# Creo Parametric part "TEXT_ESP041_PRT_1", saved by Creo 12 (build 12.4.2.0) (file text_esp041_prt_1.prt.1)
Units: Custom; MM, KILOGRAM, SECS

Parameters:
  PTC_WM_ITERATION = "0"
  PTC_WM_VERSION = "-.0"
  PTC_WM_LIFECYCLE_STATE = "In Work"
  PTC_WM_LIFECYCLE = "MO_CADDocument"
  PTC_WM_CREATED_BY = "Maximilian Roepper (Z0017RMS: MO)"
  PTC_WM_CREATED_ON = "18-Sep-26 11:36:42 AM"
  PTC_WM_MODIFIED_BY = "Maximilian Roepper (Z0017RMS: MO)"
  PTC_WM_MODIFIED_ON = "18-Sep-26 11:36:46 AM"
  PDMLINKNUMBER = "PDM000071454912"
  PTC_WM_NAME = "text_esp041_prt_1.prt"
  PTC_WM_NUMBER = "PDM000071454912"

Other parameters: WEIGHT, WEIGHT_FACTOR, WEIGHT_ADD, _MASS_TEMP, _DIFF_TEMP, MC_ERRORS, SUPPLIER

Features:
  1. coordinate system
  2. datum plane "PRT_YZ"
  3. datum plane "PRT_XY"
  4. datum plane "PRT_XZ"
  5. coordinate system
  6. datum axis
  7. datum axis
  8. datum axis
  9. coordinate system
  10. imported feature
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
Other named items: PRT, SIEMENS_MO, DRW_VIEW_ORG, PRT_X, PRT_Y, PRT_Z, CS0, ROUGH_GROB

Layers: 00_STD_CSYS-KSYS, 01_STD_PLANES-EBENEN, 02_STD_AXES-ACHSEN, 03_STD_CSYS-KSYS, 24_IMPORT_FEAT-IMPORT_KE

Surfaces: 6 plane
